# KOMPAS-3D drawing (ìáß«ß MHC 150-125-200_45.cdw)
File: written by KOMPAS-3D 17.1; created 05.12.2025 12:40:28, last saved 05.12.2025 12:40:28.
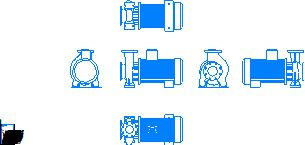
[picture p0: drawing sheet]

Sheet 1: A4, portrait

Title block, sheet 1: name: Насос MHC 150-125-200_45 / 45 кВт 3х380В; material: Сталь 10  ГОСТ 1050-88; mass: 842,83; sheets: 1; sheet format: A4

Views: Вид 1, Спереди, Проекционный вид 2, Проекционный вид 3, Проекционный вид 4, Проекционный вид 5, Проекционный вид 6
Referenced files in \\adlc.lan\data\АДЛ_ПКД\3D-модели\ADL production\Насосы ГРАНПАМП\Насосы ГРАНПАМП серии МНС\KOMPAS 3D\: Насос MHC 150-125-200_45.m3d
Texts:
  Andrey
  АДЛ
Dimensions and other numbers on the sheet: 1:1; 1; 45 кВт 3х380В; 842,83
